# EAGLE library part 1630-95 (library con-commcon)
COMPACT PCI TYPE B - 95 PINS 2mm HARD METRIC SOCKETS
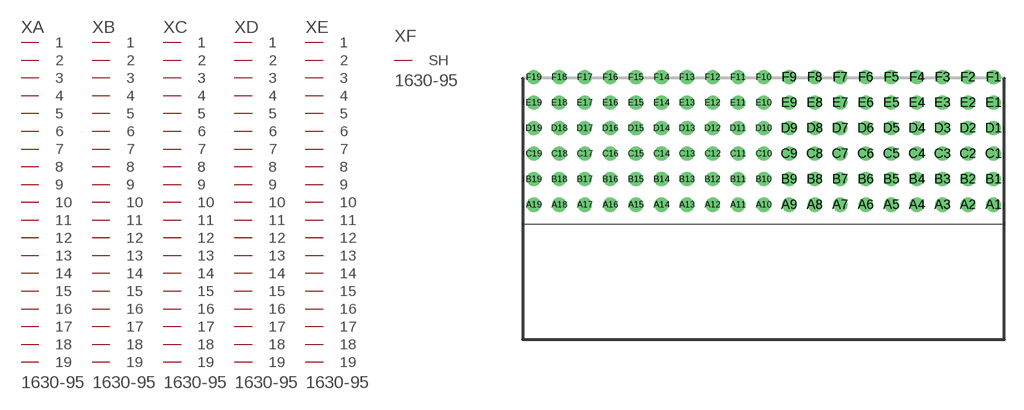
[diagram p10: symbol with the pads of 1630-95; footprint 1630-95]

Designator prefix X; gates A=PIN19 B=PIN19 C=PIN19 D=PIN19 E=PIN19 F=SHIELD

## 1630-95 (OC_FARNELL: unknown; OC_NEWARK: unknown)  [1630-95]
A1  A:1  pas
A2  A:2  pas
A3  A:3  pas
A4  A:4  pas
A5  A:5  pas
A6  A:6  pas
A7  A:7  pas
A8  A:8  pas
A9  A:9  pas
A10  A:10  pas
A11  A:11  pas
A12  A:12  pas
A13  A:13  pas
A14  A:14  pas
A15  A:15  pas
A16  A:16  pas
A17  A:17  pas
A18  A:18  pas
A19  A:19  pas
B1  B:1  pas
B2  B:2  pas
B3  B:3  pas
B4  B:4  pas
B5  B:5  pas
B6  B:6  pas
B7  B:7  pas
B8  B:8  pas
B9  B:9  pas
B10  B:10  pas
B11  B:11  pas
B12  B:12  pas
B13  B:13  pas
B14  B:14  pas
B15  B:15  pas
B16  B:16  pas
B17  B:17  pas
B18  B:18  pas
B19  B:19  pas
C1  C:1  pas
C2  C:2  pas
C3  C:3  pas
C4  C:4  pas
C5  C:5  pas
C6  C:6  pas
C7  C:7  pas
C8  C:8  pas
C9  C:9  pas
C10  C:10  pas
C11  C:11  pas
C12  C:12  pas
C13  C:13  pas
C14  C:14  pas
C15  C:15  pas
C16  C:16  pas
C17  C:17  pas
C18  C:18  pas
C19  C:19  pas
D1  D:1  pas
D2  D:2  pas
D3  D:3  pas
D4  D:4  pas
D5  D:5  pas
D6  D:6  pas
D7  D:7  pas
D8  D:8  pas
D9  D:9  pas
D10  D:10  pas
D11  D:11  pas
D12  D:12  pas
D13  D:13  pas
D14  D:14  pas
D15  D:15  pas
D16  D:16  pas
D17  D:17  pas
D18  D:18  pas
D19  D:19  pas
E1  E:1  pas
E2  E:2  pas
E3  E:3  pas
E4  E:4  pas
E5  E:5  pas
E6  E:6  pas
E7  E:7  pas
E8  E:8  pas
E9  E:9  pas
E10  E:10  pas
E11  E:11  pas
E12  E:12  pas
E13  E:13  pas
E14  E:14  pas
E15  E:15  pas
E16  E:16  pas
E17  E:17  pas
E18  E:18  pas
E19  E:19  pas
F1  F:SH  pas

## Footprint 1630-95 (pad centres in mm)
COMPACT PCI TYPE B - 95 PINS 2mm HARD METRIC SOCKETS
drill 0.6 round: A1 18,1.27; A2 16,1.27; A3 14,1.27; A4 12,1.27; A5 10,1.27; A6 8,1.27; A7 6,1.27; A8 4,1.27; A9 2,1.27; A10 0,1.27; A11 -2,1.27; A12 -4,1.27; A13 -6,1.27; A14 -8,1.27; A15 -10,1.27; A16 -12,1.27; A17 -14,1.27; A18 -16,1.27; A19 -18,1.27; B1 18,3.27; B2 16,3.27; B3 14,3.27; B4 12,3.27; B5 10,3.27; B6 8,3.27; B7 6,3.27; B8 4,3.27; B9 2,3.27; B10 0,3.27; B11 -2,3.27; B12 -4,3.27; B13 -6,3.27; B14 -8,3.27; B15 -10,3.27; B16 -12,3.27; B17 -14,3.27; B18 -16,3.27; B19 -18,3.27; C1 18,5.27; C2 16,5.27; C3 14,5.27; C4 12,5.27; C5 10,5.27; C6 8,5.27; C7 6,5.27; C8 4,5.27; C9 2,5.27; C10 0,5.27; C11 -2,5.27; C12 -4,5.27; C13 -6,5.27; C14 -8,5.27; C15 -10,5.27; C16 -12,5.27; C17 -14,5.27; C18 -16,5.27; C19 -18,5.27; D1 18,7.27; D2 16,7.27; D3 14,7.27; D4 12,7.27; D5 10,7.27; D6 8,7.27; D7 6,7.27; D8 4,7.27; D9 2,7.27; D10 0,7.27; D11 -2,7.27; D12 -4,7.27; D13 -6,7.27; D14 -8,7.27; D15 -10,7.27; D16 -12,7.27; D17 -14,7.27; D18 -16,7.27; D19 -18,7.27; E1 18,9.27; E2 16,9.27; E3 14,9.27; E4 12,9.27; E5 10,9.27; E6 8,9.27; E7 6,9.27; E8 4,9.27; E9 2,9.27; E10 0,9.27; E11 -2,9.27; E12 -4,9.27; E13 -6,9.27; E14 -8,9.27; E15 -10,9.27; E16 -12,9.27; E17 -14,9.27; E18 -16,9.27; E19 -18,9.27; F1 18,11.27; F2 16,11.27; F3 14,11.27; F4 12,11.27; F5 10,11.27; F6 8,11.27; F7 6,11.27; F8 4,11.27; F9 2,11.27; F10 0,11.27; F11 -2,11.27; F12 -4,11.27; F13 -6,11.27; F14 -8,11.27; F15 -10,11.27; F16 -12,11.27; F17 -14,11.27; F18 -16,11.27; F19 -18,11.27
